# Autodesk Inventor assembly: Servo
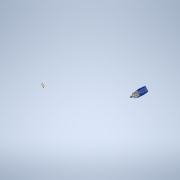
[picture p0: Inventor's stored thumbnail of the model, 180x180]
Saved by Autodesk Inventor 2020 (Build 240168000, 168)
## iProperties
Created: 2002-01
Part Number: Servo
Document SubType Name: Assemblage
Designer: Philippe
Mass: 2.28348 g
Surface Area: 60.8084 cm^2
Volume: 2.28348 cm^3
Density: 1 g/cm^3
Shininess: 41.0
Angle Display Precision: 2
Document Length Units: 11269
Document Angle Units: 11279
Document Time Units: 11290
Document Mass Units: 11283
Document Length Units Precision: 3
Document Angle Units Precision: 2
Density: 0.0
Volumn: 0.0
Area: 0.0
PropertySet Name: Model Information
Control State: 0
Master: False
Checked Out: False
Author: Philippe
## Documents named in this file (13)
- C:\Users\bruno\OneDrive\Bureau\Robot-Inventor\Robot-equilibrage\Servo\Servo.iam
- C:\Users\bruno\OneDrive\Bureau\Robot-Inventor\Robot-equilibrage\Servo\Couvercle inférieur.ipt
- C:\Users\bruno\OneDrive\Bureau\Robot-Inventor\Robot-equilibrage\Servo\Boitier.ipt
- C:\Users\bruno\OneDrive\Bureau\Robot-Inventor\Robot-equilibrage\Servo\Couvercle supérieur.ipt
- C:\Users\bruno\OneDrive\Bureau\Robot-Inventor\Robot-equilibrage\Servo\Moteur.ipt
- C:\Users\bruno\OneDrive\Bureau\Robot-Inventor\Robot-equilibrage\Servo\Pignon moteur.ipt
- C:\Users\bruno\OneDrive\Bureau\Robot-Inventor\Robot-equilibrage\Servo\Axe central.ipt
- C:\Users\bruno\OneDrive\Bureau\Robot-Inventor\Robot-equilibrage\Servo\Mobile 2-3.ipt
- C:\Users\bruno\OneDrive\Bureau\Robot-Inventor\Robot-equilibrage\Servo\Mobile 4-5.ipt
- C:\Users\bruno\OneDrive\Bureau\Robot-Inventor\Robot-equilibrage\Servo\Potentiomètre.ipt
- C:\Users\bruno\OneDrive\Bureau\Robot-Inventor\Robot-equilibrage\Servo\Mobile 6-7.ipt
- C:\Users\bruno\OneDrive\Bureau\Robot-Inventor\Robot-equilibrage\Servo\Roue 8.ipt
- C:\Users\bruno\OneDrive\Bureau\Robot-Inventor\Robot-equilibrage\Servo\ISO 7049 - ST 2.2 x 4.5 - F - H.ipt
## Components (12 placed, 12 different names)
1. Boitier:1 — Plaquage1, Plaquage2, Placage:1, Placage:2, Logement:1, Angle:1, Placage:3, Placage:4, Placage:6, Orientation, Placage:7, Logement:3, Logement:4
2. Couvercle inférieur:1 — Plaquage1, Placage:3, Placage:4
3. Couvercle supérieur:1 — Plaquage2, Placage:1, Placage:2, Angle:5
4. Moteur:1 — Logement:1, Angle:1, Logement:2
5. Pignon moteur:1 — Logement:2, Rotation:1
6. Axe central:1 — Angle:2, Placage:5, Logement:3, Angle:3, Placage:9
7. Mobile 2-3:1 — Angle:2, Placage:5, Placage:6, Rotation:1, Placage:8, Rotation:2, Placage:10
8. Mobile 4-5:1 — Orientation, Placage:7, Placage:8, Rotation:2, Rotation:3, Placage:11
9. Potentiomètre:1 — Logement:4, Placage:12
10. Mobile 6-7:1 — Angle:3, Placage:9, Placage:10, Rotation:3, Rotation:4
11. Roue 8:1 — Placage:11, Placage:12, Rotation:4, Angle:5
12. ISO 7049 - ST 2.2 x 4.5 - F - H:1
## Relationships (27: Mate 14, Angle 5, Insert 4, RelateRotation 4)
- Plaquage1 [Mate]: Boitier:1 ↔ Couvercle inférieur:1
- Plaquage2 [Mate]: Boitier:1 ↔ Couvercle supérieur:1
- Placage:1 [Mate]: Boitier:1 ↔ Couvercle supérieur:1
- Placage:2 [Mate]: Boitier:1 ↔ Couvercle supérieur:1
- Logement:1 [Insert]: Boitier:1 ↔ Moteur:1
- Angle:1: Boitier:1 ↔ Moteur:1
- Placage:3 [Mate]: Boitier:1 ↔ Couvercle inférieur:1
- Placage:4 [Mate]: Boitier:1 ↔ Couvercle inférieur:1
- Logement:2 [Insert]: Moteur:1 ↔ Pignon moteur:1
- Angle:2: Axe central:1 ↔ Mobile 2-3:1
- Placage:5 [Mate]: Axe central:1 ↔ Mobile 2-3:1
- Placage:6 [Mate]: Boitier:1 ↔ Mobile 2-3:1
- Rotation:1 [RelateRotation]: Pignon moteur:1 ↔ Mobile 2-3:1
- Orientation [Angle]: Boitier:1 ↔ Mobile 4-5:1
- Placage:7 [Mate]: Boitier:1 ↔ Mobile 4-5:1
- Placage:8 [Mate]: Mobile 2-3:1 ↔ Mobile 4-5:1
- Logement:3 [Insert]: Boitier:1 ↔ Axe central:1
- Rotation:2 [RelateRotation]: Mobile 2-3:1 ↔ Mobile 4-5:1
- Logement:4 [Insert]: Boitier:1 ↔ Potentiomètre:1
- Angle:3: Axe central:1 ↔ Mobile 6-7:1
- Placage:9 [Mate]: Axe central:1 ↔ Mobile 6-7:1
- Placage:10 [Mate]: Mobile 2-3:1 ↔ Mobile 6-7:1
- Rotation:3 [RelateRotation]: Mobile 4-5:1 ↔ Mobile 6-7:1
- Placage:11 [Mate]: Mobile 4-5:1 ↔ Roue 8:1
- Placage:12 [Mate]: Potentiomètre:1 ↔ Roue 8:1
- Rotation:4 [RelateRotation]: Mobile 6-7:1 ↔ Roue 8:1
- Angle:5: Couvercle supérieur:1 ↔ Roue 8:1
